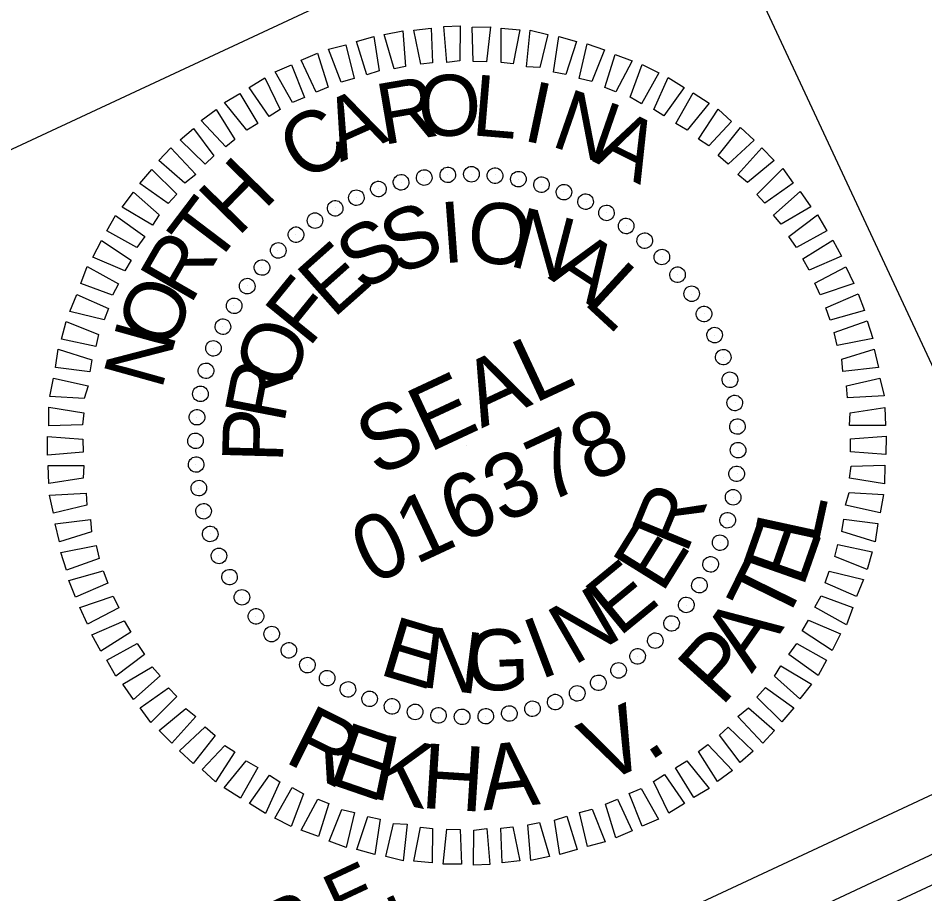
# Model space of a CAD drawing. Extents: x 2318983 to 2324558, y 920396 to 924651.
# Drawn here: x 2323618.5 to 2323819.7, y 922084.9 to 922279.2 of the extents above; entities that cross this region are included whole.
import ezdxf

# ---------------------------------------------------------------- set-up
doc = ezdxf.new("R2010")
doc.units = 0
for name, color, linetype in [('Sheet Plot Border Inside CELL', 7, 'Continuous'), ('Sheet Professional Seal CELL', 7, 'Continuous'), ('Sheet Title CELL', 7, 'Continuous')]:
    doc.layers.add(name, color=color, linetype=linetype)

msp = doc.modelspace()

# ---------------------------------------------------------------- linework, layer by layer
at = {"layer": 'Sheet Plot Border Inside CELL'}
msp.add_lwpolyline([(2320660.3, 920611.69), (2324284.61, 922303.17), (2323213.7, 924597.81), (2319589.38, 922906.33)], close=True, dxfattribs=at)
at = {"layer": 'Sheet Professional Seal CELL'}
for p, q in [((2323708.57, 922243.9), (2323708.57, 922243.9)), ((2323713.85, 922244.51), (2323713.85, 922244.51)), ((2323719.11, 922244.58), (2323719.11, 922244.58)), ((2323724.37, 922244.39), (2323724.37, 922244.39)), ((2323703.55, 922242.75), (2323703.55, 922242.75)), ((2323729.55, 922243.5), (2323729.55, 922243.5)), ((2323734.73, 922242.34), (2323734.73, 922242.34)), ((2323698.51, 922241.33), (2323698.51, 922241.33)), ((2323739.62, 922240.65), (2323739.62, 922240.65)), ((2323693.58, 922239.42), (2323693.58, 922239.42)), ((2323744.56, 922238.58), (2323744.56, 922238.58)), ((2323688.84, 922237.08), (2323688.84, 922237.08)), ((2323749.05, 922236.04), (2323749.05, 922236.04)), ((2323684.47, 922234.24), (2323684.47, 922234.24)), ((2323753.48, 922233.08), (2323753.48, 922233.08)), ((2323680.09, 922231.14), (2323680.09, 922231.14)), ((2323757.63, 922229.85), (2323757.63, 922229.85)), ((2323676.14, 922227.7), (2323676.14, 922227.7)), ((2323761.4, 922226.32), (2323761.4, 922226.32)), ((2323672.6, 922223.93), (2323672.6, 922223.93)), ((2323764.84, 922222.36), (2323764.84, 922222.36)), ((2323669.37, 922219.78), (2323669.37, 922219.78)), ((2323767.94, 922217.98), (2323767.94, 922217.98)), ((2323666.41, 922215.35), (2323666.41, 922215.35)), ((2323770.78, 922213.61), (2323770.78, 922213.61)), ((2323663.87, 922210.86), (2323663.87, 922210.86)), ((2323773.12, 922208.87), (2323773.12, 922208.87)), ((2323661.8, 922205.92), (2323661.8, 922205.92)), ((2323775.03, 922203.94), (2323775.03, 922203.94)), ((2323660.12, 922201.03), (2323660.12, 922201.03)), ((2323776.45, 922198.91), (2323776.45, 922198.91)), ((2323658.96, 922195.85), (2323658.96, 922195.85)), ((2323777.6, 922193.88), (2323777.6, 922193.88)), ((2323658.06, 922190.67), (2323658.06, 922190.67)), ((2323778.21, 922188.6), (2323778.21, 922188.6)), ((2323657.87, 922185.41), (2323657.87, 922185.41)), ((2323718.08, 922184.38), (2323718.08, 922184.38)), ((2323778.28, 922183.34), (2323778.28, 922183.34)), ((2323657.94, 922180.15), (2323657.94, 922180.15)), ((2323778.09, 922178.08), (2323778.09, 922178.08)), ((2323658.55, 922174.87), (2323658.55, 922174.87)), ((2323777.2, 922172.9), (2323777.2, 922172.9)), ((2323659.7, 922169.85), (2323659.7, 922169.85)), ((2323776.04, 922167.73), (2323776.04, 922167.73)), ((2323661.12, 922164.81), (2323661.12, 922164.81)), ((2323774.35, 922162.83), (2323774.35, 922162.83)), ((2323663.03, 922159.88), (2323663.03, 922159.88)), ((2323772.28, 922157.9), (2323772.28, 922157.9)), ((2323665.37, 922155.14), (2323665.37, 922155.14)), ((2323769.74, 922153.4), (2323769.74, 922153.4)), ((2323668.21, 922150.77), (2323668.21, 922150.77)), ((2323766.78, 922148.97), (2323766.78, 922148.97)), ((2323671.31, 922146.39), (2323671.31, 922146.39)), ((2323763.55, 922144.82), (2323763.55, 922144.82)), ((2323674.75, 922142.44), (2323674.75, 922142.44)), ((2323760.01, 922141.05), (2323760.01, 922141.05)), ((2323678.52, 922138.9), (2323678.52, 922138.9)), ((2323756.06, 922137.61), (2323756.06, 922137.61)), ((2323682.67, 922135.67), (2323682.67, 922135.67)), ((2323751.68, 922134.51), (2323751.68, 922134.51)), ((2323687.1, 922132.71), (2323687.1, 922132.71)), ((2323747.31, 922131.67), (2323747.31, 922131.67)), ((2323691.59, 922130.17), (2323691.59, 922130.17)), ((2323742.57, 922129.33), (2323742.57, 922129.33)), ((2323696.53, 922128.1), (2323696.53, 922128.1)), ((2323737.64, 922127.42), (2323737.64, 922127.42)), ((2323701.43, 922126.42), (2323701.43, 922126.42)), ((2323706.6, 922125.26), (2323706.6, 922125.26)), ((2323732.61, 922126), (2323732.61, 922126)), ((2323711.78, 922124.36), (2323711.78, 922124.36)), ((2323717.04, 922124.17), (2323717.04, 922124.17)), ((2323722.3, 922124.24), (2323722.3, 922124.24)), ((2323727.58, 922124.85), (2323727.58, 922124.85))]:
    msp.add_line(p, q, dxfattribs=at)
for points in [[(2323701.97, 922267.97), (2323699.76, 922275.54), (2323703.86, 922276.4), (2323704.51, 922268.49)], [(2323707.85, 922268.99), (2323706.34, 922276.49), (2323710.21, 922276.98), (2323710.49, 922269.3)], [(2323713.66, 922269.32), (2323712.96, 922277.34), (2323716.62, 922277.45), (2323716.51, 922269.72)], [(2323719.52, 922269.54), (2323719.24, 922277.22), (2323723.32, 922277.27), (2323722.47, 922269.46)], [(2323725.68, 922269.37), (2323725.73, 922276.94), (2323729.85, 922276.61), (2323728.36, 922269.03)], [(2323731.3, 922268.41), (2323732.16, 922276.5), (2323736.05, 922275.53), (2323734.3, 922268.22)], [(2323695.87, 922266.58), (2323693.6, 922273.99), (2323697.44, 922275.12), (2323698.63, 922267.47)], [(2323737.28, 922267.23), (2323738.51, 922275.09), (2323742.45, 922274.02), (2323740.05, 922266.67)], [(2323690.24, 922265.01), (2323687.38, 922272.28), (2323691.27, 922273.3), (2323693.06, 922265.79)], [(2323742.98, 922265.79), (2323744.8, 922273.52), (2323748.63, 922272.13), (2323745.81, 922265.12)], [(2323684.65, 922262.8), (2323681.35, 922269.87), (2323684.99, 922271.43), (2323687.31, 922263.91)], [(2323748.67, 922263.81), (2323750.96, 922271.1), (2323754.79, 922269.71), (2323751.12, 922262.83)], [(2323679.38, 922260.47), (2323675.54, 922267.29), (2323679.18, 922268.85), (2323682.04, 922261.58)], [(2323754.31, 922261.67), (2323757.02, 922268.9), (2323760.68, 922267.03), (2323756.84, 922260.21)], [(2323674.2, 922257.39), (2323669.76, 922263.79), (2323673.25, 922265.95), (2323676.66, 922258.94)], [(2323759.55, 922258.95), (2323762.74, 922266.01), (2323766.28, 922263.82), (2323761.82, 922257.5)], [(2323669.28, 922254.3), (2323664.3, 922260.45), (2323667.73, 922262.45), (2323671.74, 922255.85)], [(2323764.46, 922255.81), (2323768.29, 922262.64), (2323771.88, 922260.34), (2323766.99, 922254.35)], [(2323664.62, 922250.67), (2323659.14, 922256.46), (2323662.48, 922258.94), (2323666.65, 922252.28)], [(2323769.52, 922252.35), (2323773.83, 922259), (2323776.82, 922256.28), (2323771.78, 922250.89)], [(2323660.06, 922246.82), (2323654.52, 922252.18), (2323657.43, 922254.73), (2323661.99, 922248.65)], [(2323773.87, 922248.69), (2323778.77, 922254.94), (2323781.8, 922252.12), (2323776.08, 922246.8)], [(2323655.55, 922242.59), (2323649.78, 922247.58), (2323652.43, 922250.41), (2323657.96, 922244.52)], [(2323778.22, 922244.49), (2323783.53, 922250.41), (2323786.3, 922247.6), (2323780.37, 922242.71)], [(2323651.83, 922238.08), (2323645.51, 922242.54), (2323648.17, 922245.64), (2323653.76, 922240.17)], [(2323782.39, 922240.08), (2323788.18, 922245.83), (2323790.51, 922242.55), (2323784.22, 922238.15)], [(2323648.37, 922233.29), (2323641.61, 922237.28), (2323644.17, 922240.59), (2323649.83, 922235.55)], [(2323786.13, 922235.47), (2323792.02, 922240.74), (2323794.4, 922237.34), (2323787.85, 922233.49)], [(2323644.85, 922228.33), (2323638.24, 922232), (2323640.11, 922235.39), (2323646.64, 922230.76)], [(2323789.55, 922230.71), (2323795.9, 922235.53), (2323797.96, 922231.99), (2323791.2, 922228.3)], [(2323642.24, 922223.14), (2323635.13, 922226.18), (2323637, 922229.83), (2323643.65, 922225.52)], [(2323792.63, 922225.79), (2323799.3, 922229.96), (2323801.24, 922226.37), (2323794.07, 922223.29)], [(2323639.47, 922217.74), (2323632.45, 922220.29), (2323633.84, 922224.12), (2323640.82, 922220.23)], [(2323795.28, 922220.41), (2323802.2, 922224.03), (2323803.92, 922220.34), (2323796.5, 922217.8)], [(2323637.66, 922212.26), (2323630.03, 922214.13), (2323631.58, 922217.9), (2323638.58, 922214.81)], [(2323797.71, 922214.92), (2323804.88, 922218), (2323806.34, 922214.31), (2323798.71, 922212.21)], [(2323635.78, 922206.35), (2323628.15, 922207.96), (2323629.22, 922211.9), (2323636.39, 922209.02)], [(2323799.6, 922209.45), (2323806.87, 922212.04), (2323808.16, 922208.14), (2323800.28, 922206.58)], [(2323634.45, 922200.7), (2323626.85, 922201.66), (2323627.44, 922205.77), (2323634.89, 922203.42)], [(2323801.32, 922203.5), (2323808.47, 922205.77), (2323809.43, 922201.72), (2323801.52, 922200.81)], [(2323633.21, 922194.83), (2323625.6, 922195.25), (2323626.35, 922199.31), (2323634.04, 922197.6)], [(2323802.34, 922197.62), (2323809.74, 922199.35), (2323810.66, 922195.4), (2323802.54, 922194.93)], [(2323632.79, 922188.93), (2323625.32, 922188.76), (2323625.38, 922192.89), (2323633.13, 922191.61)], [(2323803.15, 922191.63), (2323810.8, 922192.82), (2323810.96, 922188.79), (2323803.02, 922188.79)], [(2323632.95, 922182.92), (2323625.04, 922182.27), (2323625.09, 922186.4), (2323632.92, 922185.82)], [(2323803.21, 922185.84), (2323811.12, 922186.48), (2323811.06, 922182.35), (2323803.23, 922182.94)], [(2323633, 922177.12), (2323625.35, 922175.93), (2323625.19, 922179.96), (2323633.13, 922179.96)], [(2323803.37, 922179.82), (2323810.83, 922179.99), (2323810.77, 922175.86), (2323803.02, 922177.14)], [(2323633.81, 922171.14), (2323626.41, 922169.4), (2323625.49, 922173.35), (2323633.61, 922173.82)], [(2323802.94, 922173.92), (2323810.55, 922173.5), (2323809.8, 922169.44), (2323802.11, 922171.16)], [(2323634.83, 922165.26), (2323627.68, 922162.98), (2323626.72, 922167.03), (2323634.63, 922167.95)], [(2323801.71, 922168.05), (2323809.3, 922167.1), (2323808.71, 922162.98), (2323801.26, 922165.33)], [(2323636.55, 922159.3), (2323629.28, 922156.71), (2323627.99, 922160.61), (2323635.87, 922162.17)], [(2323800.37, 922162.4), (2323808.01, 922160.8), (2323806.93, 922156.85), (2323799.76, 922159.73)], [(2323638.44, 922153.83), (2323631.27, 922150.75), (2323629.81, 922154.44), (2323637.44, 922156.54)], [(2323798.49, 922156.49), (2323806.12, 922154.62), (2323804.57, 922150.85), (2323797.57, 922153.94)], [(2323640.87, 922148.34), (2323633.95, 922144.72), (2323632.23, 922148.42), (2323639.65, 922150.95)], [(2323796.68, 922151.01), (2323803.7, 922148.46), (2323802.31, 922144.63), (2323795.33, 922148.52)], [(2323643.52, 922142.96), (2323636.85, 922138.79), (2323634.91, 922142.38), (2323642.08, 922145.47)], [(2323793.91, 922145.61), (2323801.02, 922142.57), (2323799.15, 922138.92), (2323792.5, 922143.23)], [(2323646.6, 922138.04), (2323640.25, 922133.22), (2323638.2, 922136.77), (2323644.95, 922140.45)], [(2323791.3, 922140.42), (2323797.91, 922136.75), (2323796.05, 922133.36), (2323789.51, 922138)], [(2323787.78, 922135.47), (2323794.54, 922131.47), (2323791.99, 922128.16), (2323786.32, 922133.2)], [(2323650.02, 922133.28), (2323644.13, 922128.02), (2323641.75, 922131.41), (2323648.3, 922135.26)], [(2323653.76, 922128.67), (2323647.97, 922122.92), (2323645.64, 922126.2), (2323651.93, 922130.6)], [(2323784.32, 922130.67), (2323790.64, 922126.21), (2323787.98, 922123.11), (2323782.39, 922128.58)], [(2323657.94, 922124.26), (2323652.62, 922118.34), (2323649.85, 922121.15), (2323655.78, 922126.04)], [(2323780.6, 922126.16), (2323786.37, 922121.17), (2323783.72, 922118.34), (2323778.19, 922124.24)], [(2323662.28, 922120.06), (2323657.39, 922113.81), (2323654.35, 922116.63), (2323660.07, 922121.95)], [(2323776.09, 922121.93), (2323781.63, 922116.57), (2323778.72, 922114.02), (2323774.16, 922120.1)], [(2323666.64, 922116.4), (2323662.32, 922109.76), (2323659.34, 922112.47), (2323664.37, 922117.86)], [(2323771.53, 922118.08), (2323777.01, 922112.3), (2323773.67, 922109.81), (2323769.5, 922116.47)], [(2323671.7, 922112.94), (2323667.86, 922106.12), (2323664.27, 922108.41), (2323669.16, 922114.4)], [(2323766.87, 922114.45), (2323771.85, 922108.3), (2323768.42, 922106.3), (2323764.41, 922112.9)], [(2323676.6, 922109.8), (2323673.41, 922102.75), (2323669.87, 922104.93), (2323674.33, 922111.26)], [(2323761.95, 922111.36), (2323766.4, 922104.96), (2323762.9, 922102.8), (2323759.49, 922109.82)], [(2323681.85, 922107.08), (2323679.13, 922099.85), (2323675.47, 922101.72), (2323679.31, 922108.54)], [(2323756.77, 922108.28), (2323760.61, 922101.46), (2323756.97, 922099.9), (2323754.11, 922107.17)], [(2323687.48, 922104.94), (2323685.19, 922097.65), (2323681.36, 922099.04), (2323685.03, 922105.92)], [(2323751.5, 922105.95), (2323754.8, 922098.88), (2323751.16, 922097.32), (2323748.84, 922104.84)], [(2323693.17, 922102.96), (2323691.35, 922095.23), (2323687.52, 922096.62), (2323690.34, 922103.63)], [(2323745.91, 922103.74), (2323748.77, 922096.47), (2323744.88, 922095.45), (2323743.1, 922102.96)], [(2323698.87, 922101.52), (2323697.64, 922093.66), (2323693.7, 922094.74), (2323696.1, 922102.08)], [(2323740.28, 922102.17), (2323742.55, 922094.76), (2323738.71, 922093.63), (2323737.52, 922101.28)], [(2323704.86, 922100.34), (2323703.99, 922092.26), (2323700.1, 922093.22), (2323701.85, 922100.53)], [(2323710.47, 922099.38), (2323710.42, 922091.81), (2323706.3, 922092.14), (2323707.79, 922099.72)], [(2323716.64, 922099.22), (2323716.91, 922091.53), (2323712.83, 922091.48), (2323713.68, 922099.3)], [(2323722.49, 922099.43), (2323723.19, 922091.42), (2323719.54, 922091.3), (2323719.64, 922099.03)], [(2323728.3, 922099.76), (2323729.82, 922092.26), (2323725.94, 922091.77), (2323725.66, 922099.46)], [(2323734.18, 922100.78), (2323736.39, 922093.21), (2323732.29, 922092.35), (2323731.64, 922100.26)]]:
    msp.add_lwpolyline(points, close=True, dxfattribs=at)
for centre, major_axis in [((2323713.86, 922244.42), (-0.12, 1.72)), ((2323719.11, 922244.56), (0.03, 1.73)), ((2323724.35, 922244.24), (0.18, 1.72)), ((2323703.49, 922242.77), (-0.42, 1.68)), ((2323708.64, 922243.82), (-0.27, 1.71)), ((2323729.54, 922243.47), (0.33, 1.7)), ((2323734.65, 922242.24), (0.48, 1.66)), ((2323698.46, 922241.28), (-0.56, 1.63)), ((2323739.63, 922240.58), (0.62, 1.61)), ((2323693.58, 922239.36), (-0.7, 1.58)), ((2323744.44, 922238.48), (0.76, 1.55)), ((2323688.88, 922237.01), (-0.84, 1.51)), ((2323749.06, 922235.98), (0.89, 1.48)), ((2323684.4, 922234.27), (-0.97, 1.43)), ((2323753.44, 922233.08), (1.02, 1.4)), ((2323680.18, 922231.14), (-1.09, 1.34)), ((2323757.55, 922229.82), (1.13, 1.3)), ((2323676.25, 922227.66), (-1.2, 1.24)), ((2323761.36, 922226.2), (1.24, 1.2)), ((2323672.64, 922223.85), (-1.3, 1.13)), ((2323764.84, 922222.27), (1.34, 1.09)), ((2323669.37, 922219.74), (-1.4, 1.02)), ((2323767.97, 922218.05), (1.43, 0.97)), ((2323666.47, 922215.36), (-1.48, 0.89)), ((2323770.71, 922213.57), (1.51, 0.84)), ((2323663.97, 922210.74), (-1.55, 0.76)), ((2323773.06, 922208.88), (1.58, 0.7)), ((2323661.87, 922205.93), (-1.61, 0.62)), ((2323774.98, 922203.99), (1.63, 0.56)), ((2323660.21, 922200.95), (-1.66, 0.48)), ((2323776.47, 922198.96), (1.68, 0.42)), ((2323658.99, 922195.84), (-1.7, 0.33)), ((2323777.52, 922193.81), (1.71, 0.27)), ((2323658.21, 922190.65), (-1.72, 0.18)), ((2323778.12, 922188.59), (1.72, 0.12)), ((2323657.89, 922185.41), (-1.73, 0.03)), ((2323778.26, 922183.34), (1.73, -0.03)), ((2323658.03, 922180.16), (-1.72, -0.12)), ((2323777.94, 922178.1), (1.72, -0.18)), ((2323658.63, 922174.94), (-1.71, -0.27)), ((2323777.17, 922172.91), (1.7, -0.33)), ((2323659.68, 922169.79), (-1.68, -0.42)), ((2323775.94, 922167.8), (1.66, -0.48)), ((2323661.17, 922164.76), (-1.63, -0.56)), ((2323774.28, 922162.82), (1.61, -0.62)), ((2323663.1, 922159.88), (-1.58, -0.7)), ((2323772.18, 922158.01), (1.55, -0.76)), ((2323665.44, 922155.18), (-1.51, -0.84)), ((2323769.68, 922153.39), (1.48, -0.89)), ((2323668.19, 922150.7), (-1.43, -0.97)), ((2323766.78, 922149.01), (1.4, -1.02)), ((2323671.31, 922146.48), (-1.34, -1.09)), ((2323763.52, 922144.9), (1.3, -1.13)), ((2323674.79, 922142.55), (-1.24, -1.2)), ((2323759.9, 922141.09), (1.2, -1.24)), ((2323678.6, 922138.94), (-1.13, -1.3)), ((2323755.97, 922137.61), (1.09, -1.34)), ((2323682.71, 922135.67), (-1.02, -1.4)), ((2323751.75, 922134.49), (0.97, -1.43)), ((2323687.09, 922132.77), (-0.89, -1.48)), ((2323747.27, 922131.74), (0.84, -1.51)), ((2323691.71, 922130.27), (-0.76, -1.55)), ((2323742.58, 922129.4), (0.7, -1.58)), ((2323696.52, 922128.17), (-0.62, -1.61)), ((2323737.69, 922127.47), (0.56, -1.63)), ((2323701.5, 922126.51), (-0.48, -1.66)), ((2323732.66, 922125.98), (0.42, -1.68)), ((2323706.61, 922125.29), (-0.33, -1.7)), ((2323711.8, 922124.51), (-0.18, -1.72)), ((2323717.04, 922124.19), (-0.03, -1.73)), ((2323722.29, 922124.33), (0.12, -1.72)), ((2323727.51, 922124.93), (0.27, -1.71))]:
    msp.add_ellipse(centre, major_axis=major_axis, ratio=0.999708, dxfattribs=at)
at = {"layer": 'Sheet Title CELL'}
for p, q in [((2323847.64, 922145.75), (2323685.24, 922493.72)), ((2323286.5, 922095.81), (2323766.41, 922319.78))]:
    msp.add_line(p, q, dxfattribs=at)
for points in [[(2321014.38, 920783.69), (2324233.09, 922285.88)], [(2323401.58, 921911.08), (2323836.05, 922113.85)]]:
    msp.add_lwpolyline(points, dxfattribs=at)

# ---------------------------------------------------------------- texts
at = {"layer": 'Sheet Professional Seal CELL'}
for s, height, rotation, p in [('O', 13.53, 2.4399, (2323707.47, 922252.79)), ('L', 13.53, 355.2396, (2323718.91, 922253.23)), ('R', 13.53, 9.6398, (2323699.42, 922251.02)), ('I', 13.53, 348.0388, (2323730.16, 922252.12)), ('A', 13.53, 24.039, (2323690.08, 922247.19)), ('N', 13.53, 340.8376, (2323736.41, 922250.93)), ('C', 13.53, 31.2386, (2323681.8, 922242.53)), ('A', 13.53, 333.6358, (2323745.82, 922247.51)), ('H', 13.53, 45.6382, (2323667.3, 922230.47)), ('T', 13.53, 52.8385, (2323661.91, 922223.58)), ('I', 13.53, 4.2083, (2323712.72, 922224.78)), ('O', 13.53, 354.8522, (2323717.78, 922225.29)), ('S', 13.53, 22.9191, (2323702.66, 922221.94)), ('N', 13.53, 345.4953, (2323727.1, 922224.34)), ('S', 13.53, 32.2743, (2323694.88, 922218.18)), ('R', 13.53, 60.0392, (2323656.74, 922215.34)), ('A', 13.53, 326.779, (2323735.94, 922221.58)), ('E', 13.53, 41.6298, (2323688.45, 922212.39)), ('L', 13.53, 317.4195, (2323743.68, 922216.06)), ('F', 13.53, 50.9857, (2323683.01, 922205.88)), ('O', 13.53, 67.2404, (2323652.39, 922205.1)), ('N', 13.53, 74.4422, (2323650.33, 922196.46)), ('O', 13.53, 69.6999, (2323678.83, 922196.12)), ('SEAL', 14.396, 25.0187, (2323698.08, 922177.29)), ('R', 13.53, 79.0583, (2323677.51, 922189.01)), ('P', 13.53, 88.4176, (2323677.28, 922180.43)), ('016378', 14.396, 25.0187, (2323696.99, 922153.32)), ('R', 13.53, 67.5001, (2323766.76, 922160.08)), ('L', 14.4, 77.7437, (2323795.99, 922162.05)), ('E', 13.53, 58.1428, (2323761.42, 922151.37)), ('E', 14.4, 70.6344, (2323792.63, 922152.57)), ('T', 14.4, 63.8341, (2323788.34, 922143.97)), ('E', 13.53, 39.4305, (2323751.87, 922141.75)), ('N', 13.53, 30.0751, (2323741.72, 922135.42)), ('A', 14.4, 54.9938, (2323781.3, 922133.65)), ('E', 13.53, 343.2956, (2323698.29, 922133.69)), ('I', 13.53, 20.7199, (2323734.28, 922132.35)), ('N', 13.53, 352.6526, (2323707.56, 922130.87)), ('G', 13.53, 2.0089, (2323718.11, 922129.83)), ('P', 14.4, 47.8845, (2323774.53, 922126.22)), ('V', 14.4, 25.3973, (2323748, 922109.05)), ('R', 14.4, 333.4992, (2323677.26, 922114.35)), ('E', 14.4, 340.9794, (2323686.72, 922109.63)), ('K', 14.4, 348.0888, (2323696.22, 922106.33)), ('H', 14.4, 356.3727, (2323707.69, 922103.99)), ('A', 14.4, 6.3567, (2323721.78, 922103.41)), ('.', 14.4, 33.6504, (2323758.5, 922114.12))]:
    msp.add_text(s, height=height, rotation=rotation, dxfattribs=at).set_placement(p)
at = {"layer": 'Sheet Title CELL'}
msp.add_text('P.E.', height=11.999, rotation=25.0187, dxfattribs=at).set_placement((2323676.41, 922070.73))

doc.saveas('drawing.dxf')
